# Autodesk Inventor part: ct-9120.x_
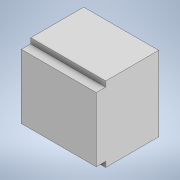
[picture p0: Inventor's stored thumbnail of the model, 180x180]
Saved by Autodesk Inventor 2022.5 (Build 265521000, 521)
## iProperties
Created: 2023-06
Part Number: ct-9120.x_
Material: Generic
Document SubType Name: Modeling
Designer: ImaoCorp
Density: 1 g/cm^3
Appearance: Default
Sending System: SOLIDWORKS 2021-2021301
MC: AMD64
MC_MODEL: Intel64 Family 6 Model 60 Stepping 3, GenuineIntel
OS: Windows_NT
FRU: Parasolid Version 32.1, build 255,  1- 1-2021
FORMAT: text
GUISE: transmit
KEY: ct-9120
FILE: ct-9120.x_t
DATE: Thu Jun 15 15:47:13 2023
Author: ImaoCorp
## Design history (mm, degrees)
feature "Base1"
node "ソリッド1"
